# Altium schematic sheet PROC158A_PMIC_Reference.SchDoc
size 431 x 279 mm; Date: Not shown in title block; ApprovedBy: Not shown in title block; CheckedBy: Not shown in title block; Author: Not shown in title block; CompanyName: Not shown in title block; Engineer: Not shown in title block; Organization: Not shown in title block; Address1: Not shown in title block; Address2: Not shown in title block; Address3: Not shown in title block; Address4: Not shown in title block; DocumentNumber: 6; Revision: Use project parameter SCH_Rev; SheetNumber: 6; SheetTotal: 24; PageSetup: Record=PageOptions¦CenterHorizontal=True¦CenterVertical=True¦PrintScale=1.00¦XCorrection=1.00¦YCorrection=1.00¦PrintKind=0¦BorderSize=5000000¦LeftOffset=0¦BottomOffset=0¦Orientation=2¦PaperLength=1000¦PaperWidth=1000¦Scale=100¦PaperSource=15¦PrintQuality=600¦MediaType=1¦DitherType=10¦PaperKind=Letter¦PrintScaleMode=1
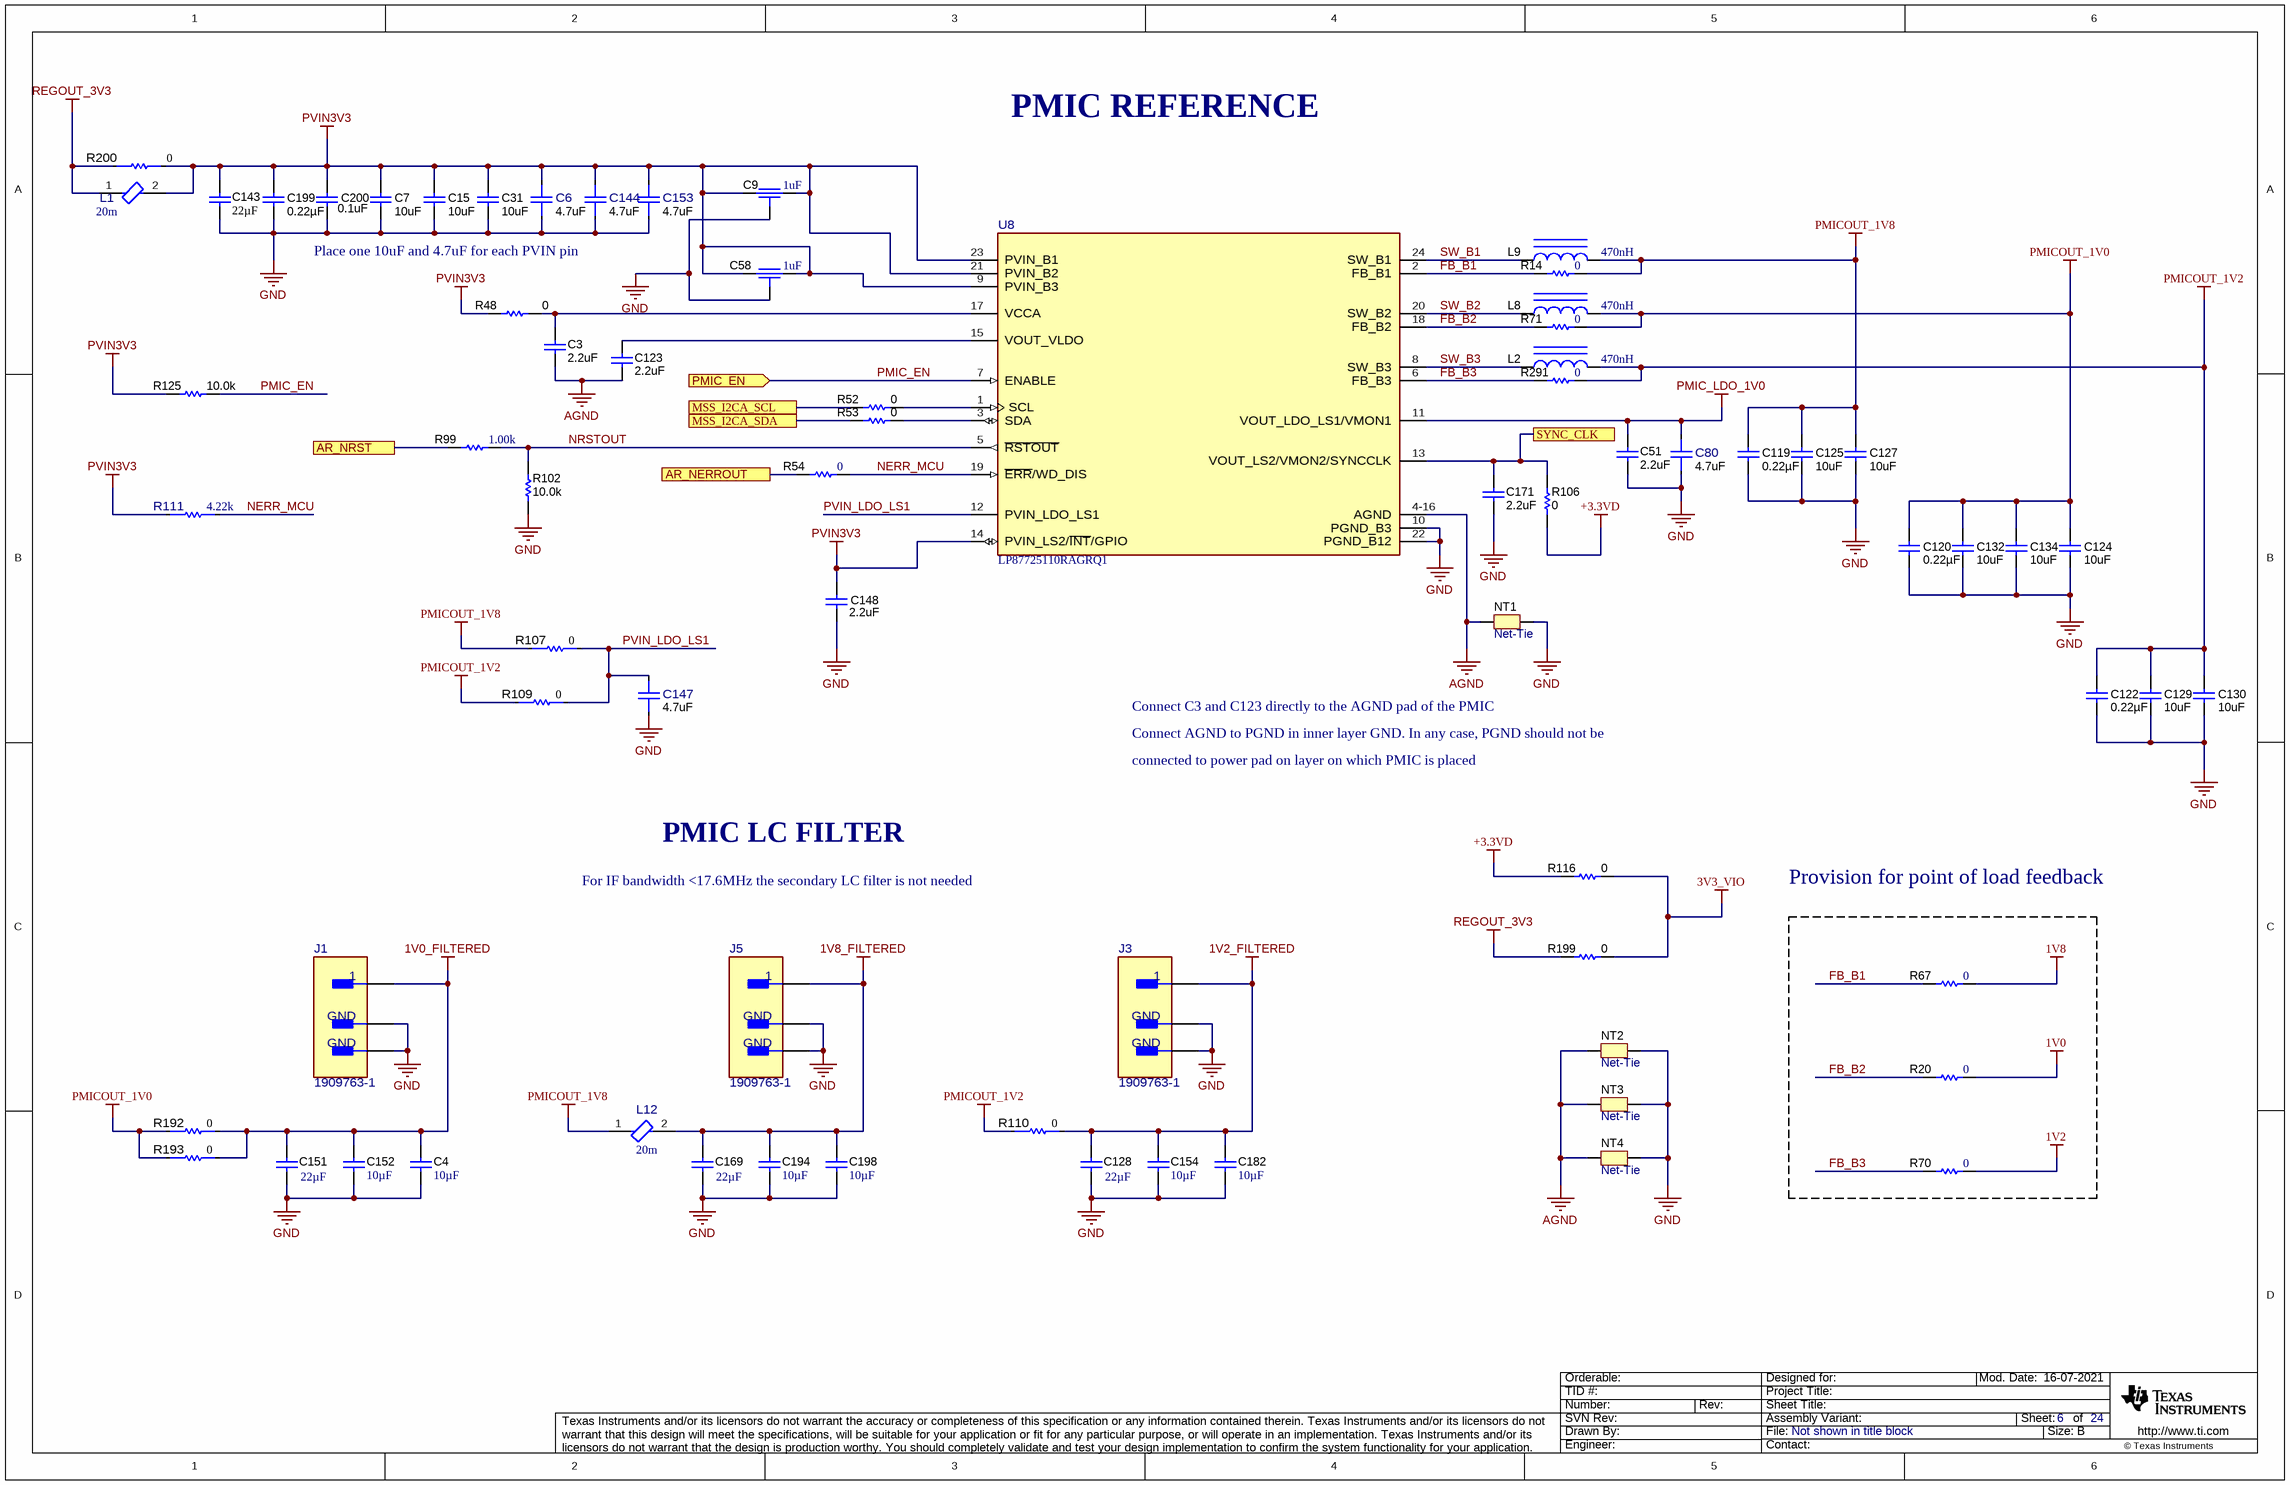
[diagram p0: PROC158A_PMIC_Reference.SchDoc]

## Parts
C3  ValueDisplayed: 2.2uF  [0603L]  (hidden comment: GCM188R70J225KE22D)
C4  Cap_F: 10µF  [0805L]  (hidden comment: C0805C106J8RACAUTO)
C6  ValueDisplayed: 4.7uF  [FP-GCJ188C70J475KE02J_0603-MFG]  (hidden comment: GCJ188C70J475KE02J)
C7  ValueDisplayed: 10uF  [0805L]  (hidden comment: GCM21BR71A106KE22L)
C9  ValueDisplayed: 1uF  [FP-NFM18HC105C1C3D_0603-MFG]  (hidden comment: NFM18HC105C1C3D)
C15  ValueDisplayed: 10uF  [0805L]  (hidden comment: GCM21BR71A106KE22L)
C31  ValueDisplayed: 10uF  [0805L]  (hidden comment: GCM21BR71A106KE22L)
C51  ValueDisplayed: 2.2uF  [0603L]  (hidden comment: GCM188R70J225KE22D)
C58  ValueDisplayed: 1uF  [FP-NFM18HC105C1C3D_0603-MFG]  (hidden comment: NFM18HC105C1C3D)
C80  ValueDisplayed: 4.7uF  [FP-GCJ188C70J475KE02J_0603-MFG]  (hidden comment: GCJ188C70J475KE02J)
C119  ValueDisplayed: 0.22µF  [0402]  (hidden comment: GCM155R71C224KE02D)
C120  ValueDisplayed: 0.22µF  [0402]  (hidden comment: GCM155R71C224KE02D)
C122  ValueDisplayed: 0.22µF  [0402]  (hidden comment: GCM155R71C224KE02D)
C123  ValueDisplayed: 2.2uF  [0603L]  (hidden comment: GCM188R70J225KE22D)
C124  ValueDisplayed: 10uF  [0805L]  (hidden comment: GCM21BR71A106KE22L)
C125  ValueDisplayed: 10uF  [0805L]  (hidden comment: GCM21BR71A106KE22L)
C127  ValueDisplayed: 10uF  [0805L]  (hidden comment: GCM21BR71A106KE22L)
C128  ValueDisplayed: 22µF  [0805_155]  (hidden comment: CGA4J1X7T0J226M)
C129  ValueDisplayed: 10uF  [0805L]  (hidden comment: GCM21BR71A106KE22L)
C130  ValueDisplayed: 10uF  [0805L]  (hidden comment: GCM21BR71A106KE22L)
C132  ValueDisplayed: 10uF  [0805L]  (hidden comment: GCM21BR71A106KE22L)
C134  ValueDisplayed: 10uF  [0805L]  (hidden comment: GCM21BR71A106KE22L)
C143  ValueDisplayed: 22µF  [0805_155]  (hidden comment: CGA4J1X7T0J226M)
C144  ValueDisplayed: 4.7uF  [FP-GCJ188C70J475KE02J_0603-MFG]  (hidden comment: GCJ188C70J475KE02J)
C147  ValueDisplayed: 4.7uF  [FP-GCJ188C70J475KE02J_0603-MFG]  (hidden comment: GCJ188C70J475KE02J)
C148  ValueDisplayed: 2.2uF  [0603L]  (hidden comment: GCM188R70J225KE22D)
C151  ValueDisplayed: 22µF  [0805_155]  (hidden comment: CGA4J1X7T0J226M)
C152  Cap_F: 10µF  [0805L]  (hidden comment: C0805C106J8RACAUTO)
C153  ValueDisplayed: 4.7uF  [FP-GCJ188C70J475KE02J_0603-MFG]  (hidden comment: GCJ188C70J475KE02J)
C154  Cap_F: 10µF  [0805L]  (hidden comment: C0805C106J8RACAUTO)
C169  ValueDisplayed: 22µF  [0805_155]  (hidden comment: CGA4J1X7T0J226M)
C171  ValueDisplayed: 2.2uF  [0603L]  (hidden comment: GCM188R70J225KE22D)
C182  Cap_F: 10µF  [0805L]  (hidden comment: C0805C106J8RACAUTO)
C194  Cap_F: 10µF  [0805L]  (hidden comment: C0805C106J8RACAUTO)
C198  Cap_F: 10µF  [0805L]  (hidden comment: C0805C106J8RACAUTO)
C199  ValueDisplayed: 0.22µF  [0402]  (hidden comment: GCM155R71C224KE02D)
C200  ValueDisplayed: 0.1uF  [0402S]  (hidden comment: GCM155R71C104KA55D)
J1  1909763-1  [FP-1909763-1_SMT_JACK _CONN-MFG]
J3  1909763-1  [FP-1909763-1_SMT_JACK _CONN-MFG]
J5  1909763-1  [FP-1909763-1_SMT_JACK _CONN-MFG]
L1  DCR_ohm: 20m  [FP-MPZ2012S101ATD25_0805-MFG]  (hidden comment: MPZ2012S101ATD25)
L2  ValueDisplayed: 470nH  [VCTA20161B]  (hidden comment: VCTA20161B-R47MS6)
L8  ValueDisplayed: 470nH  [VCTA20161B]  (hidden comment: VCTA20161B-R47MS6)
L9  ValueDisplayed: 470nH  [VCTA20161B]  (hidden comment: VCTA20161B-R47MS6)
L12  DCR_ohm: 20m  [FP-MPZ2012S101ATD25_0805-MFG]  (hidden comment: MPZ2012S101ATD25)
NT1  Net-Tie  [Net-Tie_50milWide_30milLong]  (net tie, no BOM)
NT2  Net-Tie  [Net-Tie_50milWide_30milLong]  (net tie, no BOM)
NT3  Net-Tie  [Net-Tie_50milWide_30milLong]  (net tie, no BOM)
NT4  Net-Tie  [Net-Tie_50milWide_30milLong]  (net tie, no BOM)
R14  ValueDisplayed: 0  [0402L]  (hidden comment: ERJ-2GE0R00X)
R20  ValueDisplayed: 0  [0402L]  (hidden comment: ERJ-2GE0R00X)
R48  ValueDisplayed: 0  [0402]  (hidden comment: CRCW04020000Z0EDHP)
R52  ValueDisplayed: 0  [0402L]  (hidden comment: CRCW04020000Z0EDHP)
R53  ValueDisplayed: 0  [0402L]  (hidden comment: CRCW04020000Z0EDHP)
R54  ValueDisplayed: 0  [0402L]  (hidden comment: ERJ-2GE0R00X)
R67  ValueDisplayed: 0  [0402L]  (hidden comment: ERJ-2GE0R00X)
R70  ValueDisplayed: 0  [0402L]  (hidden comment: ERJ-2GE0R00X)
R71  ValueDisplayed: 0  [0402L]  (hidden comment: ERJ-2GE0R00X)
R99  ValueDisplayed: 1.00k  [0402L]  (hidden comment: CRCW04021K00FKED)
R102  ValueDisplayed: 10.0k  [0402L]  (hidden comment: CRCW040210K0FKED)
R106  ValueDisplayed: 0  [0402L]  (hidden comment: CRCW04020000Z0EDHP)
R107  Res_ohm: 0  [FP-HCJ0603ZT0R00_0603-MFG]  (hidden comment: HCJ0603ZT0R00)
R109  Res_ohm: 0  [FP-HCJ0603ZT0R00_0603-MFG]  (hidden comment: HCJ0603ZT0R00)
R110  Res_ohm: 0  [FP-HCJ0603ZT0R00_0603-MFG]  (hidden comment: HCJ0603ZT0R00)
R111  value 4.22k  [FP-CRCW04024K22FKED_0402-MFG]  (hidden comment: CRCW04024K22FKED)
R116  ValueDisplayed: 0  [0402L]  (hidden comment: CRCW04020000Z0EDHP)
R125  ValueDisplayed: 10.0k  [0402L]  (hidden comment: CRCW040210K0FKED)
R192  Res_ohm: 0  [FP-HCJ0603ZT0R00_0603-MFG]  (hidden comment: HCJ0603ZT0R00)
R193  Res_ohm: 0  [FP-HCJ0603ZT0R00_0603-MFG]  (hidden comment: HCJ0603ZT0R00)
R199  ValueDisplayed: 0  [0402L]  (hidden comment: CRCW04020000Z0EDHP)
R200  Res_ohm: 0  [FP-HCJ0603ZT0R00_0603-MFG]  (hidden comment: HCJ0603ZT0R00)
R291  ValueDisplayed: 0  [0402L]  (hidden comment: ERJ-2GE0R00X)
U8  LP87725110RAGRQ1  [RAG0024A-MFG]

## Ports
AR_NERROUT, AR_NRST, MSS_I2CA_SCL, MSS_I2CA_SDA, PMIC_EN (in), SYNC_CLK

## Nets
1V0: R20.2
1V0_FILTERED: C4.1 C151.1 C152.1 J1.1 R192.2 R193.2
1V2: R70.2
1V2_FILTERED: C128.1 C154.1 C182.1 J3.1 R110.2
1V8: R67.2
1V8_FILTERED: C169.1 C194.1 C198.1 J5.1 L12.2
3V3_VIO: R116.2 R199.2
+3.3VD: R106.2 R116.1
AGND: C3.1 C123.1 NT1.2 NT2.1 NT3.1 NT4.1 U8.4-16(AGND)
GND: C4.2 C6.1 C7.2 C9.2 C15.2 C31.2 C51.1 C58.2 C80.1 C119.2 C120.2 C122.2 C124.2 C125.2 C127.2 C128.2 C129.2 C130.2 C132.2 C134.2 C143.2 C144.1 C147.1 C148.1 C151.2 C152.2 C153.1 C154.2 C169.2 C171.1 C182.2 C194.2 C198.2 C199.2 C200.1 J1.2(GND) J1.3(GND) J3.2(GND) J3.3(GND) J5.2(GND) J5.3(GND) NT1.1 NT2.2 NT3.2 NT4.2 R102.2 U8.10(PGND_B3) U8.22(PGND_B12)
PMIC_LDO_1V0: C51.2 C80.2 U8.11(VOUT_LDO_LS1/VMON1)
PMICOUT_1V0: C120.1 C124.1 C132.1 C134.1 L8.2 R71.2 R192.1 R193.1
PMICOUT_1V2: C122.1 C129.1 C130.1 L2.2 R109.1 R110.1 R291.2
PMICOUT_1V8: C119.1 C125.1 C127.1 L9.2 L12.1 R14.2 R107.1
PVIN3V3: C6.2 C7.1 C9.1 C9.3 C15.1 C31.1 C58.1 C58.3 C143.1 C144.2 C148.2 C153.2 C199.1 C200.2 L1.2 R48.1 R111.1 R125.2 R200.2 U8.9(PVIN_B3) U8.14(PVIN_LS2/~{INT}/GPIO) U8.21(PVIN_B2) U8.23(PVIN_B1)
REGOUT_3V3: L1.1 R199.1 R200.1
AR_NERROUT: R54.1 ; port AR_NERROUT
AR_NRST: R99.1 ; port AR_NRST
FB_B1: R14.1 R67.1 U8.2(FB_B1)
FB_B2: R20.1 R71.1 U8.18(FB_B2)
FB_B3: R70.1 R291.1 U8.6(FB_B3)
MSS_I2CA_SCL: R52.1 ; port MSS_I2CA_SCL
MSS_I2CA_SDA: R53.1 ; port MSS_I2CA_SDA
NERR_MCU: R54.2 R111.2 U8.19(~{ERR}/WD_DIS)
NRSTOUT: R99.2 R102.1 U8.5(~{RSTOUT})
PMIC_EN: R125.1 U8.7(ENABLE) ; port PMIC_EN
PVIN_LDO_LS1: C147.2 R107.2 R109.2 U8.12(PVIN_LDO_LS1)
SW_B1: L9.1 U8.24(SW_B1)
SW_B2: L8.1 U8.20(SW_B2)
SW_B3: L2.1 U8.8(SW_B3)
SYNC_CLK: C171.2 R106.1 U8.13(VOUT_LS2/VMON2/SYNCCLK) ; port SYNC_CLK
NetC3_2: C3.2 R48.2 U8.17(VCCA)
NetC123_2: C123.2 U8.15(VOUT_VLDO)
NetR52_2: R52.2 U8.1(SCL)
NetR53_2: R53.2 U8.3(SDA)

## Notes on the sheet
- PMIC REFERENCE
- Place one 10uF and 4.7uF for each PVIN pin
- Connect AGND to PGND in inner layer GND. In any case, PGND should not be
- connected to power pad on layer on which PMIC is placed
- Connect C3 and C123 directly to the AGND pad of the PMIC
- For IF bandwidth <17.6MHz the secondary LC filter is not needed
- PMIC LC FILTER
- Provision for point of load feedback

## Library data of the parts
C3 C51 C123 C148 C171 = CMP-0007134-5: CAP, CERM, 2.2 uF, 6.3 V, +/- 10%, X7R, AEC-Q200 Grade 1, 0603; Manufacturer: MuRata; TaMin_C: -55°C; Polarized: N; SizeAreaWB_mm2: 4.68; Value1: Unknown; U/M: EA; Value: 2.2uF; TaMax_C: 125°C; SizeZ_mm: 1; SizeX_mm: 1.6; SizeY_mm: 0.8; Cap_Case: 0603; Value2: 6.3V; SizeArea_mm2: 1.28; AEC Qualified: Y; Cap_F: 2.2µF; AEC Category: Q200
C4 C152 C154 C182 C194 C198 = CMP-0081061-1: CAP, CERM, 10 µF, 10 V,+/- 5%, X7R, AEC-Q200 Grade 1, 0805; Manufacturer: Kemet; TaMin_C: -55°C; Polarized: N; SizeAreaWB_mm2: 6.75; U/M: EA; Value: 10uF; TaMax_C: 125°C; SizeZ_mm: 1.45; SizeX_mm: 2; SizeY_mm: 1.25; Cap_Case: 0805; Value2: 10V; SizeArea_mm2: 2.5; AEC Qualified: Y; AEC Grade: 1; AEC Category: Q200
C6 C80 C144 C147 C153 = CMP-0091520-1: Cap Ceramic Multilayer 4.7uF 6.3V DC 10% SMD Paper T/R; Manufacturer: Murata; AEC Grade: Grade 1; TempCo: 22%; SizeZ_mm: 1mm; Temperature Characteristic: X7S; Cap_F: 4.7µF; Value: 4.7µF; AEC Qualified: Yes
C7 C15 C31 C124 C125 C127 C129 C130 C132 C134 = CMP-0008017-2: CAP, CERM, 10 uF, 10 V, +/- 10%, X7R, 0805; Manufacturer: MuRata; TaMin_C: -55°C; Polarized: N; SizeAreaWB_mm2: 6.75; Value1: Unknown; U/M: EA; Value: 10uF; TaMax_C: 125°C; SizeZ_mm: 1.45; SizeX_mm: 2; SizeY_mm: 1.25; Cap_Case: 0805; Value2: 10V; SizeArea_mm2: 2.5; Cap_F: 10µF; AEC Category: Q200
C9 C58 = CMP-0088247-2: 3 Terminals Low ESL Chip Multilayer Ceramic Capacitors for Automotive; Manufacturer: Murata; VDC_V: 16V; SizeZ_mm: 0.7mm; Tolerance_%: 20%; AEC Grade: Grade 1; Cap_F: 1µF; AEC Qualified: Yes
C119 C120 C122 C199 = CMP-0078265-1: CAP, CERM, 0.22 µF, 16 V,+/- 10%, X7R, AEC-Q200 Grade 1, 0402; Manufacturer: MuRata; TaMin_C: -55°C; Polarized: N; SizeAreaWB_mm2: 3; U/M: EA; Value: 0.22uF; TaMax_C: 125°C; SizeZ_mm: 0.6; SizeX_mm: 1; SizeY_mm: 0.5; Value2: 16V; AEC Qualified: Y; Cap_F: 220nF; AEC Category: Q200
C128 C151 C169 = CMP-0860846-1: CAP, CERM, 22 µF, 6.3 V,+/- 20%, X7T, AEC-Q200 Grade 1, 0805; Manufacturer: TDK; TaMin_C: -55°C; Polarized: N; SizeAreaWB_mm2: 6.75; U/M: EA; Value: 22uF; TaMax_C: 125°C; SizeZ_mm: 1.55; SizeX_mm: 2; SizeY_mm: 1.25; Cap_Case: 0805; Value2: 6.3V; SizeArea_mm2: 2.5; AEC Qualified: Y; AEC Grade: 1; AEC Category: Q200
C143 = CMP-0860846-1: CAP, CERM, 22 µF, 6.3 V,+/- 20%, X7T, AEC-Q200 Grade 1, 0805; Manufacturer: TDK; AEC Grade: 1; Value2: 6.3V; U/M: EA; Value: 22uF; TaMin_C: -55°C; TaMax_C: 125°C; SizeArea_mm2: 2.5; SizeAreaWB_mm2: 6.75; SizeX_mm: 2; Polarized: N; Cap_Case: 0805; AEC Qualified: Y; AEC Category: Q200; SizeZ_mm: 1.55; SizeY_mm: 1.25
C200 = CMP-0006351-2: CAP, CERM, 0.1 uF, 16 V, +/- 10%, X7R, 0402; Manufacturer: MuRata; TaMin_C: -55°C; Polarized: N; SizeAreaWB_mm2: 3; Value1: Unknown; U/M: EA; Value: 0.1uF; TaMax_C: 125°C; SizeZ_mm: 0.6; SizeX_mm: 1; SizeY_mm: 0.5; Cap_Case: 0402; Value2: 16V; Cap_F: 100nF; AEC Category: Q200
J1 J3 J5 = CMP-0091846-1: U.FL (UMCC) Connector Jack, Male Pin 50Ohm Surface Mount Solder; Manufacturer: TE Connectivity; Conn Orientation: Vertical; AEC Qualified: No; SizeZ_mm: 1.5mm; Impedance: 50Ω; Frequency_Fixed: 0-6GHz; ContactFinish: Gold,Nickel; Dielectric Material: Liquid Crystal Polymer
L1 L12 = CMP-0089947-1: 100 Ohms @ 100MHz 1 Power Line Ferrite Bead 0805 (2012 Metric) 4A 20mOhm; Manufacturer: TDK; AEC Grade: Grade 1; Impedance At Frequency: 100Ω @ 100MHz; SizeZ_mm: 1.05mm; AEC Qualified: Yes; Tolerance_%: 25%
L2 L8 L9 = CMP-0059953-1: Inductor, 470 nH, 4 A, 0.025 ohm, SMD; Manufacturer: Cyntec; Isat: 4.8A @ 30% inductance drop; Irms: 4A @ 40C rise; SizeAreaWB_mm2: 7.8; DCR_ohm: 0.025; Value: 470nH; Imax_A: 4A; SizeZ_mm: 1.2; SizeX_mm: 2; SizeY_mm: 1.6; SizeArea_mm2: 3.2; AEC Qualified: N; AEC Category: Q200
NT1 = CMP-0078142-4: Single point connection between nets.
NT2-NT4 = CMP-0078142-3: Single point connection between nets.
R14 R20 R54 R67 R70 R71 R291 = CMP-0026992-3: RES, 0, 5%, 0.1 W, AEC-Q200 Grade 0, 0402; Manufacturer: Panasonic; Power_W: 100mW; TempCo: 600 ppm/C; Value_Code: 0000; Value: 0; EIA_Code: E24; SizeX_mm: 1; SizeY_mm: 0.5; SizeZ_mm: 0.6; Value2: 0.1W; CompType: Resistor; AEC Qualified: Y; VDC_V: 50V; AEC Category: Q200; SizeAreaWB_mm2: 3; INSTALLATION: DNP
R48 R52 R53 R106 R116 R199 = CMP-0081856-1: RES, 0, 0%, 0.2 W, AEC-Q200 Grade 0, 0402; Manufacturer: Vishay-Dale; SizeAreaWB_mm2: 3; SizeArea_mm2: 0.5; AEC Qualified: Y; AEC Category: Q200; Value: 0; SizeZ_mm: 0.6; Power_W: 200mW; VDC_V: 50V; Value2: 0.2W; SizeX_mm: 1
R99 = CMP-0026071-3: RES, 1.00 k, 1%, 0.063 W, AEC-Q200 Grade 0, 0402; Manufacturer: Vishay-Dale; Power_W: 63mW; TempCo: 100 ppm/C; Value_Code: 1k00; Value: 1.00k; EIA_Code: E96; Res_ohm: 1k; SizeX_mm: 1; SizeY_mm: 0.5; SizeZ_mm: 0.6; Value2: 0.063W; AEC Qualified: Y; VDC_V: 50V; AEC Category: Q200; AEC Grade: 0
R102 R125 = CMP-0025958-3: RES, 10.0 k, 1%, 0.063 W, AEC-Q200 Grade 0, 0402; Manufacturer: Vishay-Dale; Power_W: 63mW; TempCo: 100 ppm/C; Value_Code: 10k0; Value: 10.0k; EIA_Code: E96; Res_ohm: 10k; SizeX_mm: 1; SizeY_mm: 0.5; SizeZ_mm: 0.6; Value2: 0.063W; AEC Qualified: Y; VDC_V: 50V; AEC Category: Q200; AEC Grade: 0
R107 R109 R110 R192 R193 R200 = CMP-0091690-1: RES 0 OHM JUMPER 1/4W 0603; Manufacturer: Stackpole Electronics; Power_W: 250mW; AEC Grade: Grade 0; AEC Qualified: Yes; SizeZ_mm: 0.7mm; Value: 0
R111 = CMP-0097069-1: RES Thick Film, 4.22kΩ, 1%, 0.063W, 100ppm/°C, 0402; Manufacturer: Vishay; VDC_V: 50V; AEC Qualified: Yes; AEC Grade: Grade 0; SizeZ_mm: 0.4mm; Power_W: 63mW
U8 = CMP-0097513-1: Three Buck Converters, one Linear Regulator and one Load Switch for AWR and IWR Radar Sensors, VQFN-HR24; Manufacturer: Texas Instruments; AEC Qualified: Yes; Min Supply Voltage: 3/3/3/1.2/1.6V; SizeZ_mm: 1mm; Output Voltage: 0.9-1.9/0.9-1.9/0.9-1.9/0.6-3.4V; TaMin_C: -40°C; TaMax_C: +125°C; Max Supply Voltage: 4/4/4/4/3.4V; AEC Grade: Grade 1; TJmax_C: +150°C; Standoff Height: 0mm; Number Of Outputs: 5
